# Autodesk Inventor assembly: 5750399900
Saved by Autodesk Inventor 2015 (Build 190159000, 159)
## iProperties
Created: 2020-07
Part Number: 5750399900
Checked By: TraceParts S.A.
Catalog Web Link: www.traceparts.com
Document SubType Name: Assembly
Designer: TraceParts
Company: TraceParts S.A.
Author: TraceParts
REFERENCE: 5750399900
DESIGN: HXBR-250 ECOWATT (230V50/60Hz) VE - 5750399900
SUPPLIER: Soler & Palau
TraceParts.PartNumber: 10-20122018-119605
TraceParts.PartTitle: HXBR-ECOWATT
TraceParts.InstanceId: 10-20122018-1196053LVYRPQEN6V1OJVH871U14VGW
TraceParts.PartStatus: Published
TraceParts.PartVersion: 1.0.2
TRACEPARTS: TRACEPARTS
TraceParts.PartLanguage: en
TraceParts.ClassPath: SOLER_PALAU:10-20122018-119605
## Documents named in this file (3)
- C:\TPO v2\SharedFS\Outgoing\5750399900.iam
- C:\TPO v2\SharedFS\Outgoing\5750399900_01.ipt
- C:\TPO v2\SharedFS\Outgoing\5750399900_02.ipt
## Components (2 placed, 2 different names)
1. 5750399900_01:1
2. 5750399900_02:1
